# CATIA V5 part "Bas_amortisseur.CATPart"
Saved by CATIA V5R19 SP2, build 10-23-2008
Part number: Bas_amortisseur
Bounding box of the stored display mesh (mm): x -24 to 24, y -674.825 to -627.175, z 115 to 343
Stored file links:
  G:\EU_thinkMotion\CFAO_2010\MMS_groupe3\MMS_groupe3\pmayet\pmayet_assemblage_animation\pmayet_assemblage_animation\Bas_amortisseur.CATPart
  G:\EU_thinkMotion\CFAO_2010\MMS_groupe3\MMS_groupe3\pmayet\pmayet_assemblage_animation\pmayet_assemblage_animation\pmayet_assemblage_animation.CATProduct
  G:\EU_thinkMotion\CFAO_2010\MMS_groupe3\MMS_groupe3\pmayet\pmayet_assemblage_animation\pmayet_assemblage_animation\Squelette_amortisseur.CATPart
  G:\EU_thinkMotion\CFAO_2010\MMS_groupe3\MMS_groupe3\pmayet\pmayet_assemblage_animation\pmayet_assemblage_animation\Ressort.CATPart
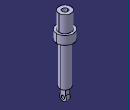
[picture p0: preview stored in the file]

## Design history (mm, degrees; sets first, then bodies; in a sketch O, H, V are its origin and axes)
Parameters
  Epaisseur_amortisseur = 6 mm
  Rayon_trou_amortisseur = 5 mm
  Hauteur_amortisseur = 80 mm
  Rayon_tige_amortisseur = 8 mm
Set1
  Plane1: linked copy from another document
  Point1 "Point.19_amortisseur": linked copy from another document
  DatumSurface1: linked copy from another document
Body1 (main body)
  Sketch1 on Plane1, origin (0, 0, 0), H (0, 1, 0), V (0, 0, 1)
    circle A1 centre (-651, 125) radius 5
    point P1 (-651, 125)
    reference projected point E1 (-651, 125) from Point1
    arc A2 centre (-651, 125) radius 10 from (-658.5, 131.6144) to (-643.5, 131.6144) ccw
    point P2 (-651, 125)
    point P3 (-658.5, 131.6144)
    point P4 (-643.5, 131.6144)
    reference projected point E2 (-651, 125) from Point1
    line L1 (-658.5, 150) -> (-643.5, 150)
    line L2 (-643.5, 150) -> (-643.5, 131.6144)
    line L3 (-658.5, 131.6144) -> (-658.5, 150)
    point P7 (-643.5, 131.6144)
    point P8 (-658.5, 131.6144)
    reference projected point E3 (-651, 125) from Point1
    reference projected point E4 (-651, 125) from Point1
    reference projected point E5 (-651, 125) from Point1
    distance P1 A1 = 5 {= Rayon_trou_amortisseur}
    radius A2 = 10 {= Rayon_trou_amortisseur *2}
    distance L1 E3 = 25 {= Rayon_trou_amortisseur *5}
    distance L3 E4 = 7.5 {= Rayon_trou_amortisseur *3/2}
    distance E5 L2 = 7.5 {= Rayon_trou_amortisseur *3/2}
    distance L3 P3 = 0
    distance L2 P4 = 0
    distance P8 P3 = 0
    distance P7 P4 = 0
    coincidence: P1 E1, P2 E2
    horizontal: L1 H
    vertical: L2 V, L3 V
  Pad1: profile Sketch1, direction (1, 0, 0), length 6 {= Epaisseur_amortisseur}, mirrored extent
  Sketch2 on face of Pad1 from Sketch1.L1, origin (0, 0, 150), H (1, 0, 0), V (0, 1, 0)
    circle A1 centre (0, -651) radius 14.4
    point P1 (0, -651)
    reference projected point E1 (0, -651) from Point1
    distance P1 A1 = 14.4 {= Rayon_tige_amortisseur  *1.8}
    coincidence: E1 P1
  Pad2: profile Sketch2, direction (0, 0, 1), length 120 {= Hauteur_amortisseur *1.5}
  Sketch3 on end face of Pad2, origin (0, 0, 270), H (1, 0, 0), V (0, 1, 0)
    circle A1 centre (0, -651) radius 24
    point P1 (0, -651)
    reference projected point E1 (0, -651) from Point1
    distance A1 P1 = 24 {= Rayon_tige_amortisseur  *3}
    coincidence: E1 P1
  Pad3: profile Sketch3, direction (0, 0, 1), up to face of DatumSurface1
  Sketch4 on end face of Pad3, origin (0, 0, 295), H (1, 0, 0), V (0, 1, 0)
    circle A1 centre (0, -651) radius 17.6
    point P1 (0, -651)
    reference projected point E1 (0, -651) from Point1
    distance A1 P1 = 17.6 {= Rayon_tige_amortisseur * 2.2}
    coincidence: E1 P1
  Pad4: profile Sketch4, direction (0, 0, 1), length 48 {= Hauteur_amortisseur *3/5}
  Sketch5 on end face of Pad4, origin (0, 0, 343), H (1, 0, 0), V (0, 1, 0)
    circle A1 centre (0, -651) radius 8
    point P1 (0, -651)
    reference projected point E1 (0, -651) from Point1
    distance A1 P1 = 8 {= Rayon_tige_amortisseur}
    coincidence: E1 P1
  Pocket1: profile Sketch5, direction (0, 0, -1), length 120 {= Hauteur_amortisseur *1.5}
Relations
  Pad3.FirstLimit.Length = Hauteur_amortisseur *2/5 (deactivated)
  Pad3.SecondLimit.Length = Hauteur_amortisseur *2/5 (deactivated)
